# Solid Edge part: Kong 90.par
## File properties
Title: Kong 90 90x42 Cm
Author: DESYS
Template: Normal.par
Last saved by: s.pallini
Revision: 12
Application: Solid Edge
Tipo di contenuto documento: 0
Precisione: 0,990
Document Number: 8053
Revision: 0
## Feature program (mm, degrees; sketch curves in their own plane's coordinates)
thicken "Assegnare_spessore_2"  Distance1 = 10 mm
thicken "Assegnare_spessore_1"  Distance1 = 10 mm
fillet "Rotondo_1" radius 30
fillet "Rotondo_2" radius 5
fillet "Rotondo_3" radius 5
sketch for "unnamed Cutout 1" plane through (0, 0, 0) normal (0, 0, 1) x-axis (1, 0, 0)
  circle centre (0, 0) radius 25
extrude "unnamed Cutout 1" cut through
sketch for "ExtrudedProtrusion_1" plane through (0, 0, 15) normal (0, 0, 1) x-axis (1, 0, 0)
extrude "ExtrudedProtrusion_1" add  Profile_Plane1_Distance = 15 mm
fillet "Rotondo_4" radius 10
sketch for "ExtrudedCutout_2" #1 plane through (0.4335, 0, 15) normal (0, 0, -1) x-axis (0, -1, 0)
sketch for "ExtrudedCutout_2" #2 plane through (0.4335, 0, 15) normal (0, 0, -1) x-axis (0, -1, 0)
extrude "ExtrudedCutout_2" cut finite 10 along -normal
fillet "Rotondo_5" radius 5
sketch for "unnamed Cutout 2" plane through (0, 0, 15) normal (0, 0, -1) x-axis (-1, 0, 0)
  arc centre (0, 0) radius 25 from (10.0481, -22.8918) to (0.5712, 24.9935) cw
  arc centre (0, 0) radius 25 from (0.5712, 24.9935) to (10.0481, -22.8918) cw
extrude "unnamed Cutout 2" cut through along -normal
Other named dimensions: "CurveByTable_2": Tolerance = 1 mm | "CurveByTable_3": Tolerance = 1 mm | "CurveByTable_4": Tolerance = 1 mm
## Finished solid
Body 1: solid body, 31 faces, 57 edges, 28 vertices.
  Faces by surface: blend 21, plane 3, cylinder 2, swept 2, offset 1, spline 1, torus 1
  Edges by curve: intersection 34, circle 22, ellipse 1
Body 2: sheet body, 1 face, 4 edges, 4 vertices.
  Faces by surface: spline 1
  Edges by curve: spline 4
Bounding box of the edges (mm; curved faces can reach further): 385.862 x 910.000 x 163.126, from (-180.1131, -460, 15) to (205.7487, 450, 178.1264).
Cylindrical faces by radius (mm): R25 x1, R35 x1
Toroidal faces (ring radius, tube radius in mm): R30 r5 x1
Planar faces by outward normal: -z 3
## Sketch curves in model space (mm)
arc centre (-18.8584, 0, 254.5842) radius 237.5842 from (-180, 0, 80) through (44.9337, 0, 25.7244) to (205, 0, 175)
circle centre (0, 0, 20) radius 25
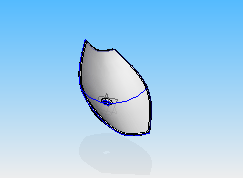
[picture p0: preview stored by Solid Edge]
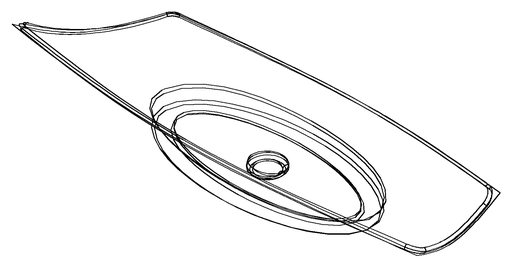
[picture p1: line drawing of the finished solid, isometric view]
